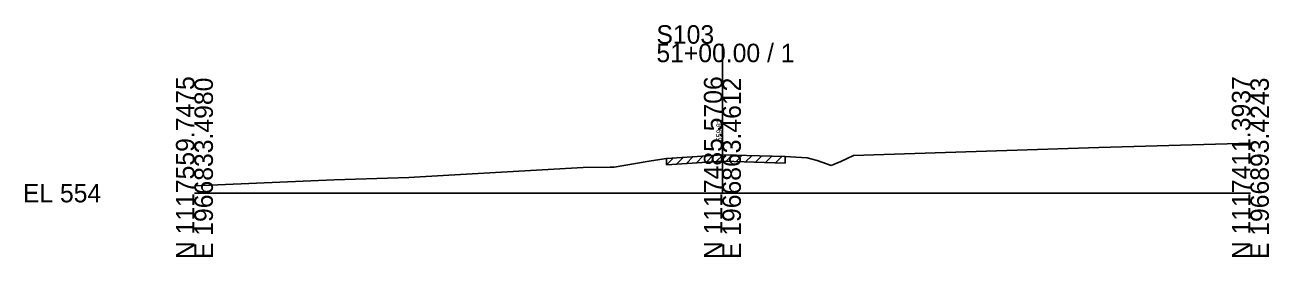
# Model space of a CAD drawing. Extents: x -26 to 163, y -10 to 45020.
# Drawn here: x -25.7 to 162.8, y 10990.3 to 11025.5 of the extents above; entities that cross this region are included whole.
import ezdxf

# ---------------------------------------------------------------- set-up
doc = ezdxf.new("R2010")
doc.units = 0
for name, color, linetype in [('RD_GPK_XS_Cell', 7, 'Continuous'), ('RD_XS_ExGround', 7, 'Continuous'), ('RD_XS_ExPaveRet', 7, 'Continuous'), ('RD_XS_TX_Elev_EX', 7, 'Continuous')]:
    doc.layers.add(name, color=color, linetype=linetype)

msp = doc.modelspace()

# ---------------------------------------------------------------- linework, layer by layer
at = {"layer": 'RD_GPK_XS_Cell'}
for p, q in [((80, 11000), (80, 11022.62)), ((0, 11000), (80, 11000)), ((80, 11000), (160, 11000))]:
    msp.add_line(p, q, dxfattribs=at)
at = {"layer": 'RD_XS_ExGround'}
for p, q in [((99.86, 11005.71), (137.06, 11006.89)), ((137.06, 11006.89), (160, 11007.54)), ((63.61, 11003.91), (68.61, 11004.78)), ((68.61, 11004.78), (69.19, 11004.87)), ((69.19, 11004.87), (71.52, 11005.26)), ((71.52, 11005.26), (72.32, 11005.31)), ((72.32, 11005.31), (80.03, 11005.81)), ((80.03, 11005.81), (81.73, 11005.76)), ((81.73, 11005.76), (89.5, 11005.54)), ((89.5, 11005.54), (91.12, 11005.42)), ((91.12, 11005.42), (92.85, 11005.32)), ((92.85, 11005.32), (94.34, 11004.91)), ((94.34, 11004.91), (96.47, 11004.2)), ((96.47, 11004.2), (97.92, 11004.77)), ((97.92, 11004.77), (99.86, 11005.71)), ((38.55, 11002.7), (58.89, 11003.85)), ((58.89, 11003.85), (62.97, 11003.9)), ((62.97, 11003.9), (63.61, 11003.91)), ((0, 11001.08), (21.15, 11001.99)), ((21.15, 11001.99), (32.51, 11002.36)), ((32.51, 11002.36), (38.55, 11002.7))]:
    msp.add_line(p, q, dxfattribs=at)
at = {"layer": 'RD_XS_ExPaveRet'}
for p, q in [((71.52, 11004.26), (72.59, 11005.33)), ((71.52, 11004.26), (71.52, 11005.26)), ((72.32, 11004.31), (80.03, 11004.81)), ((73.02, 11004.36), (74.09, 11005.43)), ((74.52, 11004.45), (75.59, 11005.52)), ((76.02, 11004.55), (77.09, 11005.62)), ((77.52, 11004.65), (78.59, 11005.72)), ((79.02, 11004.75), (80.09, 11005.81)), ((80.03, 11004.81), (81.73, 11004.76)), ((80.52, 11004.8), (81.49, 11005.77)), ((81.73, 11004.76), (89.5, 11004.54)), ((82.02, 11004.75), (82.99, 11005.73)), ((83.52, 11004.71), (84.49, 11005.68)), ((85.02, 11004.67), (85.99, 11005.64)), ((86.52, 11004.63), (87.49, 11005.6)), ((88.02, 11004.58), (88.99, 11005.55)), ((89.51, 11005.54), (89.51, 11004.54)), ((71.52, 11004.26), (72.32, 11004.31)), ((89.5, 11004.54), (89.51, 11004.54))]:
    msp.add_line(p, q, dxfattribs=at)

# ---------------------------------------------------------------- texts
at = {"layer": 'RD_GPK_XS_Cell'}
for s, p in [('S103', (70, 11022.62)), ('51+00.00 / 1', (70, 11019.82)), ('EL 554', (-26, 10998.6))]:
    msp.add_text(s, height=2.8, dxfattribs=at).set_placement(p)
for s, p in [('N 1117559.7475', (0, 10990)), ('E 1966833.4980', (2.8, 10990)), ('N 1117485.5706', (80, 10990)), ('E 1966863.4612', (82.8, 10990)), ('N 1117411.3937', (160, 10990)), ('E 1966893.4243', (162.8, 10990))]:
    msp.add_text(s, height=2.8, rotation=90, dxfattribs=at).set_placement(p)
at = {"layer": 'RD_XS_TX_Elev_EX'}
msp.add_text('559.81', height=0.8, rotation=90, dxfattribs=at).set_placement((79.9, 11007.81))

doc.saveas('drawing.dxf')
